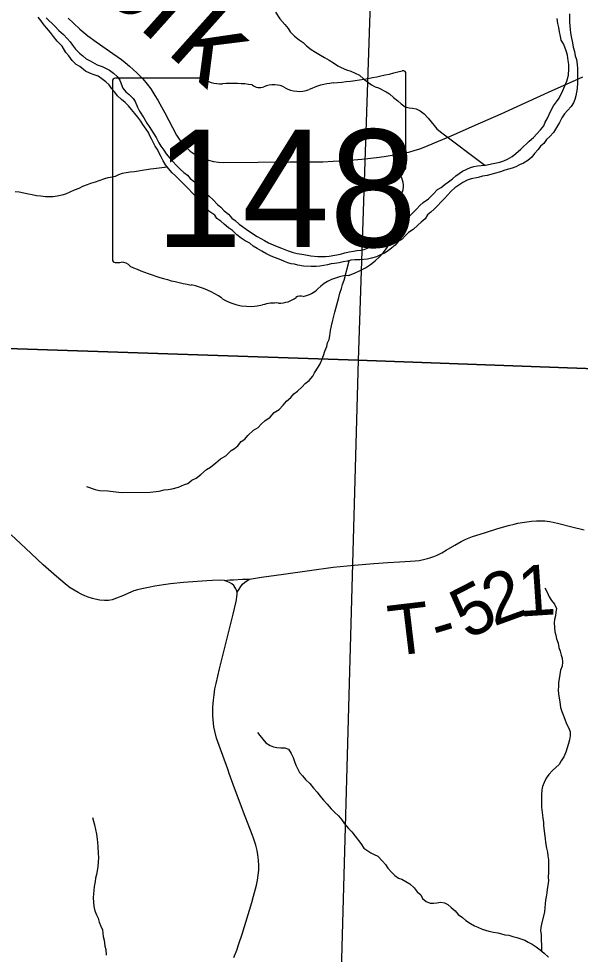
# Model space of a CAD drawing. Extents: x -7.9 to 76.1, y 0 to 22.
# Drawn here: x 7.874 to 8.505, y 15.518 to 16.568 of the extents above; entities that cross this region are included whole.
import ezdxf

# ---------------------------------------------------------------- set-up
doc = ezdxf.new("R2010")
doc.units = 0
for name, color, linetype in [('GM_X_Major_River', 7, 'Continuous'), ('GM_X_Major_River_Text', 7, 'Continuous'), ('GM_X_Minor_River', 7, 'Continuous'), ('GM_X_Section', 7, 'Continuous'), ('GM_X_State_Location', 7, 'Continuous'), ('GM_X_State_Route', 7, 'Continuous'), ('GM_X_State_Shield', 7, 'Continuous'), ('GM_X_Township_Road', 7, 'Continuous'), ('GM_X_Township_Road_Text', 7, 'Continuous'), ('SC_Scratch1', 7, 'Continuous')]:
    doc.layers.add(name, color=color, linetype=linetype)

msp = doc.modelspace()

# ---------------------------------------------------------------- linework, layer by layer
at = {"layer": 'GM_X_Major_River'}
for points in [[(8.2661, 16.2981), (8.2574, 16.2972), (8.2521, 16.2971), (8.2475, 16.2967), (8.2438, 16.2958), (8.2388, 16.295), (8.2343, 16.2938), (8.229, 16.293), (8.2252, 16.2926), (8.2214, 16.2917), (8.2173, 16.2909), (8.2127, 16.2901), (8.2086, 16.2897), (8.2029, 16.2896), (8.1942, 16.2902), (8.1881, 16.2913), (8.1843, 16.2924), (8.1805, 16.2927), (8.1767, 16.2938), (8.1729, 16.2952), (8.1687, 16.2971), (8.1629, 16.2993), (8.158, 16.3015), (8.1519, 16.3044), (8.1473, 16.307), (8.1423, 16.31), (8.1377, 16.3126), (8.1339, 16.316), (8.1286, 16.3185), (8.1244, 16.3215), (8.1194, 16.3252), (8.1144, 16.3301), (8.1102, 16.3331), (8.1052, 16.3372), (8.1013, 16.3406), (8.0971, 16.3435), (8.0948, 16.3473), (8.0891, 16.351), (8.0837, 16.3566), (8.0802, 16.3604), (8.0771, 16.3641), (8.0694, 16.3724), (8.0652, 16.3769), (8.0594, 16.3825), (8.0544, 16.3877), (8.0506, 16.3915), (8.0468, 16.3948), (8.0425, 16.3997), (8.0394, 16.4039), (8.0367, 16.4084), (8.0344, 16.4129), (8.032, 16.417), (8.0301, 16.4212), (8.0278, 16.425), (8.0239, 16.4325), (8.0215, 16.4363), (8.02, 16.44), (8.0176, 16.4438), (8.0138, 16.4491), (8.0115, 16.4528), (8.008, 16.4573), (8.0049, 16.4615), (8.001, 16.466), (7.9976, 16.4701), (7.9941, 16.4738), (7.9899, 16.4772), (7.9853, 16.4813), (7.9822, 16.4854), (7.9791, 16.4892), (7.976, 16.4937), (7.9722, 16.4971), (7.9676, 16.5004), (7.9637, 16.5034), (7.9592, 16.5049), (7.955, 16.5063), (7.9493, 16.5089), (7.9431, 16.5141), (7.9389, 16.5167), (7.9343, 16.5212), (7.9308, 16.5261), (7.9274, 16.5299), (7.9231, 16.537), (7.9177, 16.5426), (7.9135, 16.5479), (7.91, 16.5524), (7.9054, 16.5577), (7.9019, 16.5622), (7.8992, 16.5659), (7.8961, 16.5697)], [(7.9052, 16.5691), (7.9148, 16.5597), (7.9194, 16.5548), (7.9248, 16.5503), (7.9287, 16.5458), (7.9321, 16.5421), (7.9348, 16.5383), (7.9383, 16.5338), (7.9425, 16.5293), (7.9464, 16.5263), (7.9502, 16.523), (7.9548, 16.5208), (7.9624, 16.5163), (7.9681, 16.5141), (7.972, 16.5123), (7.9762, 16.51), (7.9808, 16.5067), (7.985, 16.503), (7.9881, 16.4988), (7.9896, 16.495), (7.9912, 16.4901), (7.9947, 16.486), (7.9985, 16.483), (8.0031, 16.4785), (8.0051, 16.4748), (8.0078, 16.4687), (8.0102, 16.4642), (8.0148, 16.4567), (8.0183, 16.4506), (8.021, 16.4469), (8.0237, 16.4427), (8.0261, 16.4386), (8.0288, 16.4345)], [(8.4929, 16.5735), (8.493, 16.564), (8.4939, 16.556), (8.4943, 16.5522), (8.4948, 16.5481), (8.4964, 16.5409), (8.4972, 16.536), (8.4988, 16.531), (8.4996, 16.5261), (8.5008, 16.5223), (8.5016, 16.5167), (8.5021, 16.5121), (8.5022, 16.5003), (8.5019, 16.4961), (8.5016, 16.4897), (8.5009, 16.4855), (8.5002, 16.4813), (8.4991, 16.4771), (8.4977, 16.4733), (8.4951, 16.4695), (8.491, 16.4649), (8.4876, 16.461), (8.4846, 16.4568), (8.4817, 16.4514), (8.475, 16.44), (8.4709, 16.4357), (8.4671, 16.4323), (8.4642, 16.428), (8.4604, 16.4249), (8.4578, 16.4211), (8.4537, 16.4165), (8.4507, 16.4123), (8.4462, 16.4088), (8.4413, 16.4057), (8.4368, 16.4037), (8.4327, 16.4018), (8.4285, 16.4002), (8.4247, 16.399), (8.4206, 16.3978), (8.4157, 16.3962), (8.41, 16.3946), (8.4047, 16.393), (8.4006, 16.3918), (8.3953, 16.391), (8.3904, 16.3898), (8.3828, 16.3882), (8.3783, 16.3866), (8.3734, 16.3842), (8.3644, 16.378), (8.3602, 16.3742), (8.3561, 16.3699), (8.3528, 16.3661), (8.3412, 16.3542), (8.3374, 16.3507), (8.3337, 16.3476), (8.3311, 16.3434), (8.3266, 16.3395), (8.3228, 16.3361), (8.3176, 16.3311), (8.3123, 16.3279), (8.3086, 16.3241), (8.3052, 16.3203), (8.3007, 16.3179), (8.2974, 16.3137), (8.2936, 16.3106), (8.2895, 16.3075), (8.2854, 16.3048), (8.2808, 16.3028), (8.2763, 16.3005), (8.2706, 16.2989), (8.2661, 16.2981)], [(8.4901, 16.4979), (8.4919, 16.5044), (8.4922, 16.5116), (8.4922, 16.5165), (8.4917, 16.5211), (8.4909, 16.5271), (8.4893, 16.5317), (8.4877, 16.5358), (8.4862, 16.5396), (8.4838, 16.5437), (8.483, 16.5479), (8.4818, 16.5532), (8.481, 16.5581), (8.4801, 16.5627), (8.4793, 16.568)], [(8.0288, 16.4345), (8.0319, 16.4284), (8.0342, 16.4247), (8.0373, 16.4205), (8.04, 16.4164), (8.0442, 16.4115), (8.0477, 16.4074), (8.0512, 16.4036), (8.0562, 16.3988), (8.06, 16.3954), (8.0639, 16.3924), (8.0669, 16.3887), (8.0719, 16.3849), (8.0808, 16.3763), (8.0842, 16.3722), (8.0881, 16.3692), (8.0927, 16.3647), (8.0977, 16.3595), (8.1015, 16.3565), (8.1053, 16.3524), (8.11, 16.3483), (8.1138, 16.3441), (8.1176, 16.3415), (8.1219, 16.3374), (8.1257, 16.3348), (8.1299, 16.3315), (8.1337, 16.3292), (8.1421, 16.3233), (8.1506, 16.3188), (8.1551, 16.3162), (8.1601, 16.314), (8.1647, 16.3122), (8.1696, 16.3104), (8.1734, 16.3089), (8.1772, 16.3074), (8.1826, 16.3056), (8.1872, 16.3042), (8.1925, 16.3035), (8.1986, 16.3024), (8.2024, 16.3017), (8.2103, 16.3011), (8.2153, 16.3008), (8.219, 16.3008), (8.2232, 16.3013), (8.2357, 16.3037), (8.2406, 16.3049), (8.2455, 16.3061), (8.2504, 16.307), (8.2542, 16.3078), (8.2588, 16.3082), (8.2625, 16.309), (8.2671, 16.3106), (8.2708, 16.3122), (8.2746, 16.3141), (8.2795, 16.3172), (8.2878, 16.3234), (8.2919, 16.3261), (8.296, 16.33), (8.3009, 16.3331), (8.305, 16.3377), (8.3095, 16.3427), (8.314, 16.347), (8.3177, 16.3508), (8.3215, 16.3543), (8.3248, 16.3581), (8.3286, 16.3616), (8.3346, 16.3658), (8.3398, 16.3709), (8.3447, 16.3762), (8.3488, 16.3786), (8.3533, 16.3821), (8.3571, 16.3848), (8.3616, 16.3882), (8.3653, 16.3917), (8.3691, 16.394), (8.3728, 16.3968), (8.3819, 16.4007), (8.3857, 16.4019), (8.3898, 16.4027), (8.394, 16.4031), (8.3989, 16.4036), (8.4072, 16.4052), (8.4148, 16.4068), (8.4193, 16.4084), (8.4235, 16.4104), (8.4287, 16.4131), (8.4329, 16.4166), (8.4385, 16.4216), (8.4478, 16.4305), (8.4527, 16.4347), (8.4564, 16.4386), (8.4605, 16.4432), (8.4643, 16.4478), (8.4657, 16.4516), (8.468, 16.4554), (8.472, 16.4646), (8.475, 16.4703), (8.4783, 16.4746), (8.4813, 16.4788), (8.4857, 16.4872), (8.4901, 16.4979)]]:
    msp.add_lwpolyline(points, dxfattribs=at)
at = {"layer": 'GM_X_Minor_River'}
for points in [[(8.163, 16.5753), (8.1676, 16.5678), (8.1734, 16.5614), (8.1769, 16.5569), (8.1792, 16.5531), (8.1842, 16.5483), (8.1896, 16.5442), (8.1938, 16.5412), (8.1976, 16.5375), (8.203, 16.5334), (8.2076, 16.5304), (8.2133, 16.527), (8.2179, 16.5244)], [(8.2179, 16.5244), (8.2232, 16.5215), (8.2278, 16.5185), (8.2328, 16.5152), (8.2366, 16.5133), (8.2427, 16.5107), (8.2473, 16.5089), (8.2572, 16.5045), (8.2618, 16.5004), (8.266, 16.497), (8.2706, 16.4937), (8.2748, 16.4915), (8.2786, 16.4904), (8.287, 16.4859), (8.2909, 16.4837), (8.2955, 16.4796), (8.3001, 16.4759), (8.3039, 16.4725), (8.3085, 16.4691), (8.3131, 16.4677), (8.3169, 16.4674), (8.3207, 16.4667), (8.3253, 16.4644), (8.3299, 16.4611), (8.3345, 16.4562), (8.3376, 16.4521), (8.341, 16.448), (8.3441, 16.4442), (8.3483, 16.4408), (8.3979, 16.4035)], [(7.8703, 16.3741), (7.8749, 16.3734), (7.8802, 16.3724), (7.8852, 16.3713), (7.8893, 16.3706), (7.8943, 16.3695), (7.8992, 16.3689), (7.9045, 16.3685), (7.9083, 16.3682), (7.9129, 16.3683), (7.9174, 16.3691), (7.9231, 16.3703), (7.9272, 16.3715), (7.9322, 16.3735), (7.937, 16.3758), (7.9423, 16.3778), (7.9465, 16.3798), (7.9518, 16.3817), (7.9555, 16.3833), (7.9608, 16.3849), (7.9646, 16.3861), (7.971, 16.3885), (7.9748, 16.3897), (7.9793, 16.3905), (7.9831, 16.3913), (7.9869, 16.3932), (7.991, 16.3944), (7.9952, 16.3953), (7.9997, 16.3961), (8.0043, 16.3965), (8.0088, 16.397), (8.013, 16.3978), (8.0179, 16.3986), (8.0224, 16.3994), (8.0262, 16.3999), (8.041, 16.4017)], [(7.9507, 16.0427), (7.9602, 16.0394), (7.9652, 16.0383), (7.9743, 16.0377), (7.9864, 16.0363), (7.9906, 16.036), (8.0221, 16.0365), (8.0323, 16.0374), (8.0379, 16.039), (8.0421, 16.0394), (8.0467, 16.0402), (8.0538, 16.0419), (8.0606, 16.045), (8.0644, 16.0462), (8.0689, 16.0497), (8.0738, 16.052), (8.079, 16.0563), (8.0854, 16.0617), (8.0899, 16.0644), (8.0959, 16.0694), (8.1012, 16.0736), (8.1072, 16.0771), (8.1132, 16.0833), (8.1169, 16.0853), (8.1207, 16.0883), (8.1244, 16.0933), (8.1282, 16.0957), (8.1319, 16.0999), (8.1383, 16.1061), (8.1432, 16.1088), (8.1469, 16.1126), (8.151, 16.1165), (8.1567, 16.1204), (8.1615, 16.1257), (8.1668, 16.1292), (8.1713, 16.1339), (8.175, 16.1385), (8.1799, 16.1427), (8.1836, 16.1466), (8.1874, 16.1496), (8.1926, 16.1547), (8.1963, 16.1585), (8.2005, 16.1616), (8.2046, 16.1666), (8.2068, 16.1704), (8.2109, 16.1766), (8.2131, 16.1804), (8.2149, 16.185), (8.2168, 16.1899), (8.2182, 16.1945), (8.2204, 16.1998), (8.2211, 16.204), (8.223, 16.2079), (8.2237, 16.212), (8.2247, 16.2177), (8.2258, 16.2231), (8.2272, 16.2296), (8.2283, 16.2341), (8.2294, 16.2383), (8.2341, 16.2551), (8.2352, 16.2597), (8.237, 16.265), (8.2381, 16.2696), (8.2399, 16.2742), (8.2454, 16.2962)], [(8.4653, 15.9288), (8.468, 15.9239), (8.4703, 15.919), (8.4727, 15.9149), (8.4761, 15.9107), (8.4785, 15.9058), (8.4778, 15.9017), (8.4775, 15.8975), (8.4764, 15.8933), (8.4757, 15.8895), (8.4766, 15.8796), (8.4778, 15.8758), (8.4786, 15.8717), (8.4802, 15.8668), (8.481, 15.8619), (8.4826, 15.8577), (8.4837, 15.8535), (8.4849, 15.8498), (8.4854, 15.8456), (8.4847, 15.841), (8.4828, 15.8364), (8.4821, 15.8315), (8.4808, 15.8224), (8.4808, 15.8186), (8.4805, 15.814), (8.4809, 15.8098), (8.4814, 15.8049), (8.4822, 15.8008), (8.483, 15.7947), (8.4846, 15.7902), (8.4858, 15.7864), (8.4878, 15.7815), (8.4897, 15.7762), (8.4924, 15.7713), (8.494, 15.7671), (8.4937, 15.7626), (8.493, 15.7584), (8.4919, 15.7542), (8.489, 15.7443), (8.4868, 15.7393), (8.4838, 15.7347), (8.4816, 15.7305), (8.4779, 15.7274), (8.4741, 15.724), (8.47, 15.7194), (8.4667, 15.7151), (8.4645, 15.7105), (8.4626, 15.706), (8.4619, 15.7022), (8.4616, 15.6965), (8.4618, 15.6828), (8.4627, 15.6737), (8.4631, 15.6699), (8.4639, 15.6658), (8.464, 15.662), (8.4649, 15.6529), (8.4657, 15.6476), (8.4661, 15.643), (8.4673, 15.6366), (8.4682, 15.632), (8.4686, 15.6279), (8.4694, 15.6237), (8.4696, 15.6097), (8.4693, 15.604), (8.4694, 15.5998), (8.4687, 15.5948), (8.468, 15.5907), (8.4676, 15.5865), (8.467, 15.5819), (8.4662, 15.5781), (8.4659, 15.5743), (8.4652, 15.5697), (8.4649, 15.5652), (8.4617, 15.5515), (8.461, 15.5477), (8.4606, 15.5439), (8.4611, 15.5397), (8.4616, 15.5214)], [(8.1425, 15.7667), (8.1452, 15.763), (8.1487, 15.7589), (8.1521, 15.7551), (8.1567, 15.7521), (8.1606, 15.7503), (8.1644, 15.7496), (8.1689, 15.7493), (8.1735, 15.7493), (8.1773, 15.7479), (8.1804, 15.743), (8.1827, 15.7385), (8.1843, 15.7339), (8.1855, 15.7298), (8.1878, 15.7253), (8.1898, 15.7215), (8.1932, 15.7177), (8.1967, 15.7136), (8.2013, 15.7091), (8.2055, 15.7039), (8.2098, 15.6994), (8.2125, 15.6956), (8.2167, 15.6907), (8.221, 15.6862), (8.2252, 15.681), (8.229, 15.6769), (8.2336, 15.6728), (8.2375, 15.6686), (8.2402, 15.6641), (8.2448, 15.6589), (8.2487, 15.6551), (8.2525, 15.6502), (8.2587, 15.642), (8.2622, 15.6367), (8.2699, 15.6315), (8.2737, 15.6297), (8.2779, 15.6275), (8.2829, 15.6222), (8.2863, 15.6185), (8.289, 15.6143), (8.2933, 15.6098), (8.2967, 15.6061), (8.301, 15.6031), (8.3048, 15.602), (8.3093, 15.5994), (8.3136, 15.5965), (8.3185, 15.592), (8.322, 15.5878), (8.3259, 15.5841), (8.3278, 15.58), (8.332, 15.5766), (8.3366, 15.5748), (8.3404, 15.5748), (8.3442, 15.5752), (8.3487, 15.5761), (8.3525, 15.5754), (8.3563, 15.5735), (8.3602, 15.5702), (8.3648, 15.5664), (8.3682, 15.5623), (8.3728, 15.559), (8.3767, 15.5556), (8.3817, 15.5522), (8.3862, 15.5493), (8.3901, 15.5478), (8.395, 15.5456), (8.4026, 15.5434), (8.4076, 15.5424), (8.4125, 15.5417), (8.4167, 15.5406), (8.4205, 15.5395), (8.4251, 15.5388), (8.4296, 15.5374), (8.4338, 15.5363), (8.443, 15.5334), (8.4468, 15.5312), (8.451, 15.5289), (8.4556, 15.526), (8.4602, 15.5226), (8.4648, 15.5189), (8.4694, 15.5144)], [(7.9572, 15.6711), (7.9596, 15.6628), (7.9617, 15.6522), (7.9625, 15.6469), (7.9629, 15.6431), (7.9634, 15.6386), (7.9635, 15.6306), (7.9639, 15.6261), (7.9636, 15.6208), (7.9633, 15.6162), (7.9626, 15.6113), (7.9619, 15.6071), (7.9608, 15.6029), (7.9601, 15.5991), (7.959, 15.5937), (7.9587, 15.5892), (7.9584, 15.5854), (7.9581, 15.5808), (7.9582, 15.5759), (7.9586, 15.571), (7.9598, 15.5664), (7.9618, 15.5619), (7.9637, 15.5581), (7.9649, 15.5536), (7.9665, 15.5491), (7.9684, 15.5449), (7.9693, 15.5373), (7.9705, 15.5332), (7.9713, 15.5267), (7.9721, 15.523), (7.9726, 15.5165)]]:
    msp.add_lwpolyline(points, dxfattribs=at)
at = {"layer": 'GM_X_Section'}
for points in [[(7.2713, 17.2194), (8.2894, 17.1874), (8.2558, 16.1845), (7.2312, 16.2186)], [(8.2558, 16.1845), (8.2275, 15.1763), (7.1984, 15.2096), (7.2312, 16.2186)]]:
    msp.add_lwpolyline(points, close=True, dxfattribs=at)
at = {"layer": 'GM_X_State_Route'}
for points in [[(7.9301, 16.5687), (7.9358, 16.563), (7.9429, 16.5563), (7.9522, 16.5487), (7.9614, 16.5419), (7.9802, 16.5287), (7.9897, 16.5221), (7.9938, 16.5188), (7.9988, 16.5147), (8.007, 16.5073), (8.0137, 16.5003), (8.0188, 16.4944), (8.0227, 16.4891), (8.0274, 16.4817), (8.0305, 16.4764), (8.033, 16.4722), (8.0384, 16.4623), (8.0518, 16.4371), (8.0552, 16.4316), (8.0577, 16.4285), (8.062, 16.4236), (8.0671, 16.4193), (8.0713, 16.4162), (8.0763, 16.4133), (8.0821, 16.4108), (8.0875, 16.4091), (8.093, 16.4078), (8.0987, 16.407), (8.1049, 16.4066), (8.1435, 16.4068), (8.179, 16.4071), (8.2161, 16.4074), (8.2275, 16.4079), (8.2464, 16.409), (8.2598, 16.4102), (8.2763, 16.412), (8.285, 16.4132), (8.294, 16.4146), (8.3031, 16.4163), (8.3089, 16.4174), (8.3136, 16.4186), (8.3187, 16.42), (8.325, 16.422), (8.3317, 16.4244), (8.3416, 16.4286), (8.3595, 16.4361), (8.3871, 16.4484), (8.4163, 16.4613), (8.4431, 16.4734), (8.4737, 16.4872), (8.4965, 16.4975), (8.5082, 16.5027)], [(8.116, 15.5139), (8.1194, 15.5222), (8.1218, 15.5291), (8.1253, 15.54), (8.1361, 15.5758), (8.1382, 15.5826), (8.1413, 15.5952), (8.1425, 15.6008), (8.1435, 15.6062), (8.144, 15.6118), (8.1441, 15.6173), (8.1438, 15.6233), (8.1431, 15.6291), (8.1423, 15.6342), (8.1408, 15.6399), (8.1386, 15.6466), (8.1368, 15.652), (8.127, 15.6771), (8.1209, 15.6933), (8.1158, 15.707), (8.1119, 15.7175), (8.1112, 15.7195), (8.1091, 15.7253), (8.0994, 15.7521), (8.0967, 15.7602), (8.0946, 15.768), (8.0936, 15.7729), (8.0927, 15.781), (8.0924, 15.7854), (8.0926, 15.7948), (8.0932, 15.803), (8.0939, 15.809), (8.0948, 15.8154), (8.096, 15.8214), (8.0998, 15.8381), (8.1076, 15.8693), (8.1151, 15.8993), (8.1184, 15.9121), (8.119, 15.9156), (8.1195, 15.9193), (8.1197, 15.9217), (8.1196, 15.9239), (8.119, 15.9264), (8.1183, 15.928), (8.1173, 15.9297), (8.1161, 15.9314), (8.1139, 15.9336), (8.1111, 15.9351), (8.1056, 15.9372), (8.1005, 15.9374), (8.0922, 15.9371), (8.0857, 15.9367), (8.0595, 15.9349), (8.0448, 15.9335), (8.037, 15.9325), (8.0271, 15.9309), (8.0201, 15.9295), (8.0125, 15.9278), (8.0078, 15.9267), (8.0038, 15.9254), (7.9978, 15.9231), (7.9921, 15.9204), (7.9844, 15.9172), (7.9793, 15.9156), (7.9751, 15.9148), (7.9708, 15.9147), (7.9655, 15.9151), (7.9602, 15.9161), (7.9572, 15.917), (7.9525, 15.9185), (7.9487, 15.9201), (7.9445, 15.9219), (7.9411, 15.9238), (7.9367, 15.9262), (7.9322, 15.9291), (7.9287, 15.9317), (7.9194, 15.9394), (7.914, 15.9442), (7.9019, 15.9549), (7.8885, 15.9674), (7.8765, 15.9786), (7.8658, 15.9886)]]:
    msp.add_lwpolyline(points, dxfattribs=at)
at = {"layer": 'GM_X_State_Shield'}
for p, q in [((8.3093, 16.4014), (8.3093, 16.5061)), ((7.9798, 16.4977), (7.9798, 16.2976)), ((8.0795, 16.5011), (7.983, 16.5011)), ((8.3093, 16.4014), (8.3093, 16.4014))]:
    msp.add_line(p, q, dxfattribs=at)
for centre, major_axis, start_param, end_param in [((8.1919, 16.774), (0.3495, 0), 4.814394, 5.042369), ((8.3057, 16.5065), (0.00367, 0), 6.141152, 7.989035), ((7.9835, 16.4981), (0.00382, 0), 1.712693, 3.28349), ((8.1025, 16.5244), (0.037, 0), 4.042523, 4.731795), ((8.1148, 16.3888), (0.133, 0), 1.404758, 1.657858), ((8.145, 16.4991), (0.0107, 0), 3.836095, 5.185415), ((8.1607, 16.476), (0.0222, 0), 0.950623, 2.079405), ((8.2365, 16.44), (0.0703, 0), 1.699011, 2.107814), ((8.1893, 16.5077), (0.0267, 0), 4.081561, 5.145723), ((8.3085, 16.3937), (0.00568, 0), 1.883978, 3.671073), ((8.3054, 16.401), (0.00393, 0), 5.05454, 6.418171), ((8.2724, 16.3805), (0.0341, 0), 5.934695, 6.695948), ((8.3225, 16.3576), (0.0248, 0), 2.387724, 3.262537), ((8.2115, 16.3443), (0.0874, 0), 5.101752, 6.440018), ((7.9836, 16.2971), (0.00385, 0), 3.00124, 4.508301), ((7.9841, 16.3176), (0.0294, 0), 4.665946, 4.897461), ((7.9902, 16.286), (0.0106, 0), 0.519207, 1.627899), ((8.124, 16.4658), (0.2524, 0), 4.195997, 4.488961), ((8.2484, 16.2414), (0.0479, 0), 1.647645, 2.488434), ((8.0487, 16.2077), (0.079, 0), 0.823519, 1.323587), ((8.1877, 16.2782), (0.0282, 0), 4.937069, 5.64225), ((8.1342, 16.285), (0.0501, 0), 4.026481, 4.996735), ((8.1668, 16.27), (0.0267, 0), 4.691044, 5.507374), ((8.1909, 16.2506), (0.00752, 0), 1.147584, 2.315152), ((8.1631, 16.2158), (0.0412, 0), 1.495662, 1.94098)]:
    msp.add_ellipse(centre, major_axis=major_axis, ratio=0.8, start_param=start_param, end_param=end_param, dxfattribs=at)
at = {"layer": 'GM_X_Township_Road'}
for points in [[(8.1056, 15.9372), (8.1114, 15.9378), (8.1157, 15.9381), (8.1257, 15.9385), (8.1338, 15.9387), (8.1471, 15.9409), (8.1717, 15.9444), (8.2009, 15.9485), (8.2275, 15.9521), (8.2511, 15.9545), (8.2732, 15.9563), (8.2889, 15.9574), (8.3023, 15.9583), (8.3142, 15.9589), (8.3197, 15.9592), (8.3244, 15.9598), (8.329, 15.9606), (8.3334, 15.9617), (8.3362, 15.9625), (8.3406, 15.9641), (8.3446, 15.9657), (8.3495, 15.9683), (8.3545, 15.9711), (8.3642, 15.9769), (8.3715, 15.981), (8.375, 15.9828), (8.3784, 15.9842), (8.3841, 15.9864), (8.3975, 15.9907), (8.4124, 15.9956), (8.4247, 15.999), (8.4309, 16.0006), (8.4352, 16.0015), (8.4426, 16.0028), (8.4504, 16.0038), (8.4562, 16.0042), (8.4615, 16.0043), (8.4654, 16.0041), (8.4706, 16.0035), (8.4748, 16.0027), (8.481, 16.0012), (8.4958, 15.9975), (8.5095, 15.994)], [(8.1196, 15.9239), (8.1219, 15.9274), (8.1239, 15.9304), (8.1259, 15.9329), (8.128, 15.9348), (8.1305, 15.9367), (8.1338, 15.9387)]]:
    msp.add_lwpolyline(points, dxfattribs=at)
at = {"layer": 'SC_Scratch1'}
for points in [[(8.9, 16.161), (8.9, 17.1682), (8.2894, 17.1874), (8.2558, 16.1845)], [(8.9, 15.1537), (8.9, 16.161), (8.2558, 16.1845), (8.2275, 15.1763)]]:
    msp.add_lwpolyline(points, close=True, dxfattribs=at)

# ---------------------------------------------------------------- texts
at = {"layer": 'GM_X_Major_River_Text'}
msp.add_text('Fork', height=0.09471, rotation=318.147, dxfattribs=at).set_placement((7.8977, 16.657))
at = {"layer": 'GM_X_State_Location'}
for s in ['s', 'r']:
    msp.add_text(s, height=0.000189, dxfattribs=at).set_placement((8.1408, 16.3843))
msp.add_text('148', height=0.000189, rotation=0, dxfattribs=at).set_placement((8.074, 16.3705))
at = {"layer": 'GM_X_State_Shield'}
msp.add_text('148', height=0.13184, dxfattribs=at).set_placement((8.0274, 16.3117))
at = {"layer": 'GM_X_Township_Road_Text'}
for s, rotation, p in [('2', 19.9524, (8.4079, 15.8854)), ('1', 3.8279, (8.4367, 15.8965)), ('5', 27.0837, (8.3785, 15.8702)), ('T', 6.8045, (8.293, 15.8521)), ('-', 16.6781, (8.3457, 15.8593))]:
    msp.add_text(s, height=0.0568, rotation=rotation, dxfattribs=at).set_placement(p)

doc.saveas('drawing.dxf')
